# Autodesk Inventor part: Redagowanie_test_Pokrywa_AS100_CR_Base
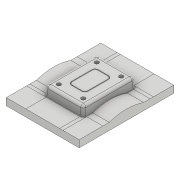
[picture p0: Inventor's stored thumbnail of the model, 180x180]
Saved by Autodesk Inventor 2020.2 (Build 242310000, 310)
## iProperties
Created: 2015-11
Part Number: Redagowanie_test_Pokrywa_AS100_CR_Base
Material: Ogólne
Document SubType Name: Modeling
Designer: F.Stasiak
Density: 1 g/cm^3
Appearance: Domyślne
Catalog Web Link: www.expertbooks.pl
Manager: www.cadconsulting.pl
Company: Fabian Stasiak CAD Consulting
Author: F.Stasiak
Subject: Zbiór ćwiczeń. Autodesk Inventor 2020. Kurs Professional
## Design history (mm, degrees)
node "Redagowanie_test_Pokrywa_AS100_MP"
feature "Bryła5::Redagowanie_test_Pokrywa_AS100_MP"
tag "Bryła wyprowadzona2"
node "Bryła2"
feature "Redagowanie_test_Pokrywa_AS100_MP_Bodies"
